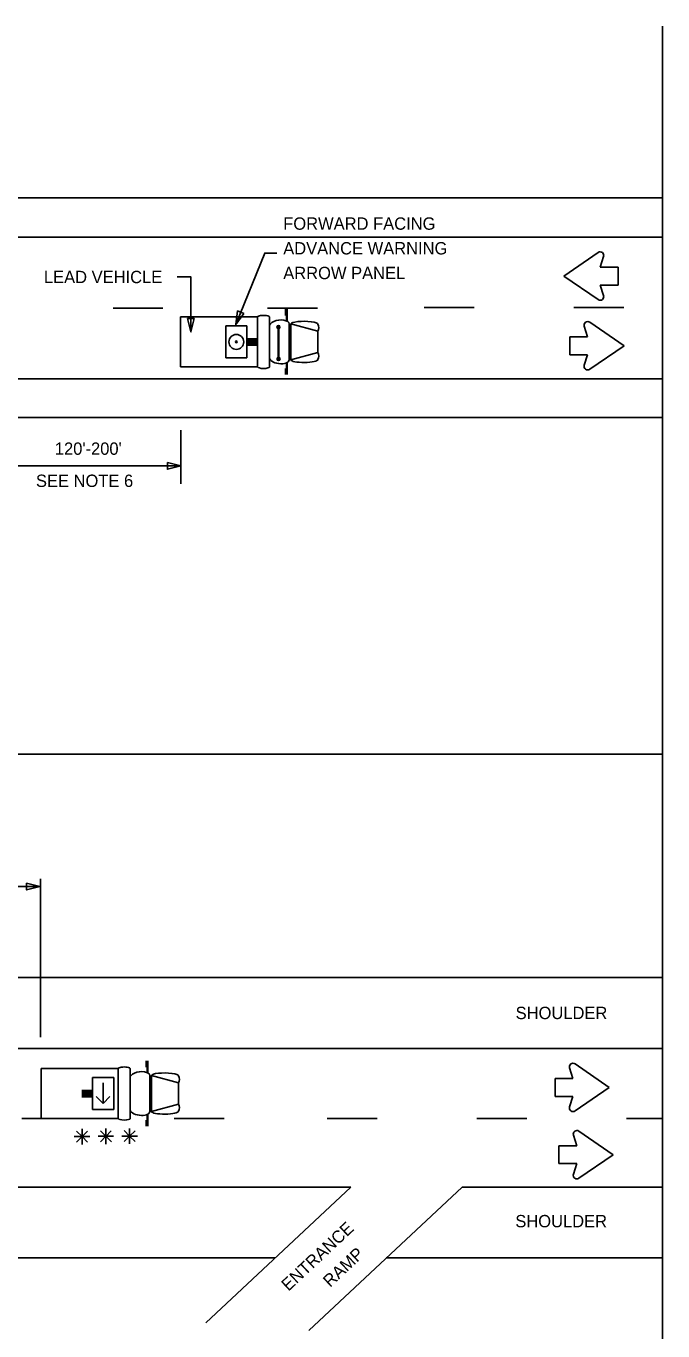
# Model space of a CAD drawing. Extents: x 1373848 to 1374003, y 380642 to 381248.
# Drawn here: x 1373897.2 to 1373928.1, y 381017.9 to 381081.3 of the extents above; entities that cross this region are included whole.
import ezdxf

# ---------------------------------------------------------------- set-up
doc = ezdxf.new("R2010")
doc.units = 0
doc.layers.add('Working Level 1', color=7, linetype='Continuous')

msp = doc.modelspace()

# ---------------------------------------------------------------- linework, layer by layer
at = {"layer": 'Working Level 1'}
for p, q in [((1373928.123, 381081.277), (1373928.123, 380977.045)), ((1373848.144, 381072.933), (1373928.119, 381072.933)), ((1373848.144, 381071.021), (1373928.119, 381071.021)), ((1373923.333, 381069.138), (1373925, 381070.281)), ((1373925.105, 381069.574), (1373925.268, 381070.082)), ((1373925.973, 381069.574), (1373925.105, 381069.574)), ((1373925.973, 381069.574), (1373925.973, 381068.701)), ((1373923.333, 381069.138), (1373925, 381067.994)), ((1373925.973, 381068.701), (1373925.105, 381068.701)), ((1373925.105, 381068.701), (1373925.268, 381068.194)), ((1373909.8, 381067.223), (1373909.8, 381067.52)), ((1373909.847, 381066.937), (1373909.847, 381067.52)), ((1373909.887, 381066.937), (1373909.887, 381067.52)), ((1373904.695, 381067.151), (1373904.695, 381064.725)), ((1373904.695, 381067.15), (1373908.449, 381067.15)), ((1373904.695, 381064.725), (1373904.695, 381067.15)), ((1373908.449, 381065.938), (1373908.449, 381067.15)), ((1373909.025, 381065.938), (1373909.025, 381067.15)), ((1373909.988, 381065.938), (1373909.988, 381066.811)), ((1373910.068, 381066.811), (1373911.381, 381066.452)), ((1373910.068, 381065.938), (1373910.068, 381066.811)), ((1373926.262, 381065.752), (1373924.595, 381066.896)), ((1373906.9, 381066.714), (1373907.926, 381066.714)), ((1373906.9, 381066.714), (1373906.9, 381065.162)), ((1373907.926, 381065.162), (1373907.926, 381066.714)), ((1373909.391, 381066.675), (1373909.391, 381066.675)), ((1373909.453, 381066.64), (1373909.453, 381065.135)), ((1373909.457, 381066.64), (1373909.457, 381065.135)), ((1373909.462, 381066.64), (1373909.462, 381065.135)), ((1373909.47, 381066.64), (1373909.47, 381065.135)), ((1373909.479, 381066.726), (1373909.479, 381066.726)), ((1373909.481, 381066.64), (1373909.481, 381065.135)), ((1373911.381, 381065.938), (1373911.381, 381066.452)), ((1373923.623, 381065.315), (1373923.623, 381066.188)), ((1373923.623, 381066.188), (1373924.49, 381066.188)), ((1373924.49, 381066.188), (1373924.327, 381066.696)), ((1373907.926, 381066.093), (1373908.449, 381066.093)), ((1373907.926, 381066.015), (1373908.449, 381066.015)), ((1373907.926, 381065.938), (1373908.449, 381065.938)), ((1373907.926, 381065.86), (1373908.449, 381065.86)), ((1373907.926, 381065.783), (1373908.449, 381065.783)), ((1373908.449, 381065.938), (1373908.449, 381064.725)), ((1373909.025, 381065.938), (1373909.025, 381064.725)), ((1373909.988, 381065.938), (1373909.988, 381065.064)), ((1373910.068, 381065.938), (1373910.068, 381065.064)), ((1373911.381, 381065.938), (1373911.381, 381065.423)), ((1373926.262, 381065.752), (1373924.595, 381064.608)), ((1373906.9, 381065.162), (1373907.926, 381065.162)), ((1373909.396, 381065.122), (1373909.396, 381065.122)), ((1373909.483, 381065.173), (1373909.483, 381065.173)), ((1373909.847, 381064.938), (1373909.847, 381064.356)), ((1373909.887, 381064.938), (1373909.887, 381064.356)), ((1373910.068, 381065.064), (1373911.381, 381065.423)), ((1373923.623, 381065.315), (1373924.49, 381065.315)), ((1373924.49, 381065.315), (1373924.327, 381064.808)), ((1373904.695, 381064.725), (1373908.449, 381064.725)), ((1373909.8, 381064.653), (1373909.8, 381064.356)), ((1373848.144, 381064.151), (1373928.119, 381064.151)), ((1373848.144, 381062.263), (1373928.119, 381062.263)), ((1373904.711, 381061.657), (1373904.711, 381059.04)), ((1373896.382, 381059.911), (1373904.711, 381059.911)), ((1373848.144, 381045.913), (1373928.15, 381045.913)), ((1373897.894, 381039.85), (1373897.894, 381032.162)), ((1373891.479, 381039.48), (1373897.894, 381039.48)), ((1373848.144, 381035.059), (1373928.15, 381035.059)), ((1373877.242, 381031.611), (1373928.15, 381031.611)), ((1373897.921, 381030.642), (1373897.921, 381028.216)), ((1373897.921, 381030.641), (1373901.675, 381030.641)), ((1373897.921, 381028.216), (1373897.921, 381030.641)), ((1373901.675, 381029.429), (1373901.675, 381030.641)), ((1373902.25, 381029.429), (1373902.25, 381030.641)), ((1373903.026, 381030.714), (1373903.026, 381031.011)), ((1373903.073, 381030.428), (1373903.073, 381031.011)), ((1373903.113, 381030.428), (1373903.113, 381031.011)), ((1373923.772, 381030.164), (1373923.609, 381030.671)), ((1373925.544, 381029.728), (1373923.877, 381030.871)), ((1373901.455, 381030.205), (1373900.429, 381030.205)), ((1373900.429, 381028.652), (1373900.429, 381030.205)), ((1373901.455, 381030.205), (1373901.455, 381028.652)), ((1373903.214, 381029.429), (1373903.214, 381030.302)), ((1373903.294, 381030.302), (1373904.607, 381029.943)), ((1373903.294, 381029.429), (1373903.294, 381030.302)), ((1373922.905, 381029.291), (1373922.905, 381030.164)), ((1373922.905, 381030.164), (1373923.772, 381030.164)), ((1373900.429, 381029.583), (1373899.906, 381029.583)), ((1373900.429, 381029.506), (1373899.906, 381029.506)), ((1373900.429, 381029.428), (1373899.906, 381029.428)), ((1373900.942, 381029.941), (1373900.942, 381028.948)), ((1373901.675, 381029.429), (1373901.675, 381028.216)), ((1373902.25, 381029.429), (1373902.25, 381028.216)), ((1373903.214, 381029.429), (1373903.214, 381028.555)), ((1373903.294, 381029.429), (1373903.294, 381028.555)), ((1373904.607, 381029.429), (1373904.607, 381029.943)), ((1373904.607, 381029.429), (1373904.607, 381028.914)), ((1373925.544, 381029.728), (1373923.877, 381028.584)), ((1373900.429, 381029.351), (1373899.906, 381029.351)), ((1373900.429, 381029.273), (1373899.906, 381029.273)), ((1373900.942, 381028.948), (1373900.604, 381029.286)), ((1373900.942, 381028.948), (1373901.271, 381029.278)), ((1373903.294, 381028.555), (1373904.607, 381028.914)), ((1373922.905, 381029.291), (1373923.772, 381029.291)), ((1373923.772, 381029.291), (1373923.609, 381028.784)), ((1373897.921, 381028.216), (1373901.675, 381028.216)), ((1373901.455, 381028.652), (1373900.429, 381028.652)), ((1373903.026, 381028.143), (1373903.026, 381027.847)), ((1373903.073, 381028.429), (1373903.073, 381027.847)), ((1373903.113, 381028.429), (1373903.113, 381027.847)), ((1373926.385, 381028.212), (1373928.15, 381028.212)), ((1373899.911, 381027.337), (1373899.645, 381027.603)), ((1373899.905, 381027.332), (1373900.171, 381027.598)), ((1373899.911, 381027.337), (1373899.911, 381027.714)), ((1373901.073, 381027.353), (1373900.807, 381027.619)), ((1373901.067, 381027.348), (1373901.333, 381027.614)), ((1373901.073, 381027.353), (1373901.073, 381027.73)), ((1373902.227, 381027.361), (1373901.961, 381027.627)), ((1373902.22, 381027.356), (1373902.487, 381027.622)), ((1373902.227, 381027.361), (1373902.227, 381027.738)), ((1373925.733, 381026.459), (1373924.066, 381027.603)), ((1373899.911, 381027.337), (1373899.535, 381027.337)), ((1373899.911, 381027.337), (1373899.645, 381027.071)), ((1373899.911, 381027.337), (1373900.177, 381027.071)), ((1373899.911, 381027.337), (1373899.911, 381026.961)), ((1373899.911, 381027.337), (1373900.287, 381027.337)), ((1373901.073, 381027.353), (1373900.697, 381027.353)), ((1373901.073, 381027.353), (1373900.807, 381027.087)), ((1373901.073, 381027.353), (1373901.339, 381027.087)), ((1373901.073, 381027.353), (1373901.073, 381026.977)), ((1373901.073, 381027.353), (1373901.449, 381027.353)), ((1373902.227, 381027.361), (1373901.85, 381027.361)), ((1373902.227, 381027.361), (1373901.961, 381027.095)), ((1373902.227, 381027.361), (1373902.493, 381027.095)), ((1373902.227, 381027.361), (1373902.227, 381026.985)), ((1373902.227, 381027.361), (1373902.603, 381027.361)), ((1373923.093, 381026.023), (1373923.093, 381026.896)), ((1373923.093, 381026.896), (1373923.961, 381026.896)), ((1373923.961, 381026.896), (1373923.798, 381027.403)), ((1373925.733, 381026.459), (1373924.066, 381025.316)), ((1373923.093, 381026.023), (1373923.961, 381026.023)), ((1373923.961, 381026.023), (1373923.798, 381025.515)), ((1373848.144, 381024.889), (1373912.979, 381024.889)), ((1373912.979, 381024.889), (1373905.926, 381018.294)), ((1373918.391, 381024.889), (1373910.943, 381017.925)), ((1373918.391, 381024.889), (1373928.15, 381024.889)), ((1373848.144, 381021.441), (1373909.291, 381021.441)), ((1373914.703, 381021.441), (1373928.15, 381021.441))]:
    msp.add_line(p, q, dxfattribs=at)
for points in [[(1373907.383, 381066.776), (1373908.797, 381070.255), (1373909.375, 381070.255)], [(1373905.203, 381066.422), (1373905.203, 381069.091), (1373904.54, 381069.091)], [(1373901.42, 381067.575), (1373903.845, 381067.575)], [(1373908.933, 381067.575), (1373911.359, 381067.575)], [(1373916.549, 381067.609), (1373918.974, 381067.609)], [(1373923.824, 381067.609), (1373926.25, 381067.609)], [(1373909.389, 381066.649), (1373909.416, 381066.603)], [(1373909.391, 381066.675), (1373909.44, 381066.59)], [(1373909.397, 381066.693), (1373909.459, 381066.587)], [(1373909.406, 381066.707), (1373909.475, 381066.588)], [(1373909.417, 381066.717), (1373909.489, 381066.593)], [(1373909.429, 381066.725), (1373909.502, 381066.599)], [(1373909.444, 381066.729), (1373909.513, 381066.609)], [(1373909.459, 381066.733), (1373909.523, 381066.622)], [(1373909.477, 381066.73), (1373909.53, 381066.638)], [(1373909.498, 381066.722), (1373909.534, 381066.661)], [(1373909.394, 381065.096), (1373909.42, 381065.05)], [(1373909.396, 381065.122), (1373909.444, 381065.037)], [(1373909.402, 381065.14), (1373909.463, 381065.034)], [(1373909.411, 381065.154), (1373909.479, 381065.035)], [(1373909.421, 381065.164), (1373909.493, 381065.04)], [(1373909.433, 381065.172), (1373909.506, 381065.046)], [(1373909.448, 381065.176), (1373909.517, 381065.056)], [(1373909.463, 381065.179), (1373909.527, 381065.069)], [(1373909.481, 381065.177), (1373909.534, 381065.085)], [(1373909.503, 381065.169), (1373909.538, 381065.108)], [(1373896.983, 381028.212), (1373899.408, 381028.212)], [(1373904.39, 381028.212), (1373906.816, 381028.212)], [(1373911.834, 381028.212), (1373914.26, 381028.212)], [(1373919.11, 381028.212), (1373921.535, 381028.212)]]:
    msp.add_lwpolyline(points, dxfattribs=at)
for points in [[(1373907.778, 381067.317), (1373907.383, 381066.776), (1373907.477, 381067.44)], [(1373905.365, 381067.072), (1373905.203, 381066.422), (1373905.04, 381067.072)], [(1373904.061, 381060.073), (1373904.711, 381059.911), (1373904.061, 381059.748)], [(1373897.217, 381039.643), (1373897.867, 381039.48), (1373897.217, 381039.318)]]:
    msp.add_lwpolyline(points, close=True, dxfattribs=at)
for centre, radius in [((1373907.413, 381065.938), 0.362), ((1373909.461, 381066.66), 0.0728), ((1373907.413, 381065.938), 0.0451), ((1373909.465, 381065.107), 0.0728)]:
    msp.add_circle(centre, radius, dxfattribs=at)
for centre, radius, start, end in [((1373925.1, 381070.135), 0.177, 342.18241, 124.44548), ((1373925.1, 381068.14), 0.177, 235.55454, 17.81761), ((1373911.06, 381066.624), 0.364, 331.88006, 28.11991), ((1373924.495, 381066.75), 0.177, 55.55454, 197.81761), ((1373911.06, 381065.252), 0.364, 331.88008, 28.11994), ((1373924.495, 381064.754), 0.177, 162.1824, 304.44547), ((1373923.778, 381030.725), 0.177, 55.55454, 197.81761), ((1373904.285, 381030.115), 0.364, 331.88006, 28.11991), ((1373904.285, 381028.743), 0.364, 331.88008, 28.11994), ((1373923.778, 381028.73), 0.177, 162.1824, 304.44547), ((1373923.966, 381027.457), 0.177, 55.55454, 197.81761), ((1373923.966, 381025.461), 0.177, 162.1824, 304.44547)]:
    msp.add_arc(centre, radius, start, end, dxfattribs=at)
for centre, major_axis, ratio, start_param, end_param in [((1373908.737, 381067.15), (0.288, 0), 0.269913, 0, 3.141593), ((1373909.506, 381066.752), (0.482, 0.06), 0.503092, 0, 3.141593), ((1373910.725, 381066.804), (0.656, -0.008), 0.2034, 0, 3.141593), ((1373909.506, 381065.124), (0.482, -0.06), 0.503092, 3.141593, 6.283185), ((1373910.725, 381065.072), (0.656, 0.008), 0.2034, 3.141593, 6.283185), ((1373908.737, 381064.725), (0.288, 0), 0.269913, 3.141593, 6.283185), ((1373901.963, 381030.641), (0.288, 0), 0.269913, 0, 3.141593), ((1373902.732, 381030.243), (0.482, 0.06), 0.503092, 0, 3.141593), ((1373903.95, 381030.295), (0.656, -0.008), 0.2034, 0, 3.141593), ((1373901.963, 381028.216), (0.288, 0), 0.269913, 3.141593, 6.283185), ((1373902.732, 381028.615), (0.482, -0.06), 0.503092, 3.141593, 6.283185), ((1373903.95, 381028.563), (0.656, 0.008), 0.2034, 3.141593, 6.283185)]:
    msp.add_ellipse(centre, major_axis=major_axis, ratio=ratio, start_param=start_param, end_param=end_param, dxfattribs=at)

# ---------------------------------------------------------------- texts
for s, p in [('FORWARD FACING', (1373909.693, 381071.385)), ('ADVANCE WARNING ', (1373909.693, 381070.185)), ('LEAD VEHICLE', (1373898.06, 381068.791)), ('ARROW PANEL', (1373909.693, 381068.985)), ("120'-200'", (1373898.59, 381060.453)), ('SEE NOTE 6', (1373897.672, 381058.891))]:
    msp.add_text(s, height=0.6, dxfattribs=at).set_placement(p)
for s, rotation, p in [('SHOULDER', 0, (1373920.99, 381033.044)), ('ENTRANCE', 43.07908, (1373909.946, 381019.8)), ('SHOULDER', 0, (1373920.974, 381022.931)), ('RAMP', 43.07908, (1373911.97, 381019.985))]:
    msp.add_text(s, height=0.6, rotation=rotation, dxfattribs=at).set_placement(p)

doc.saveas('drawing.dxf')
